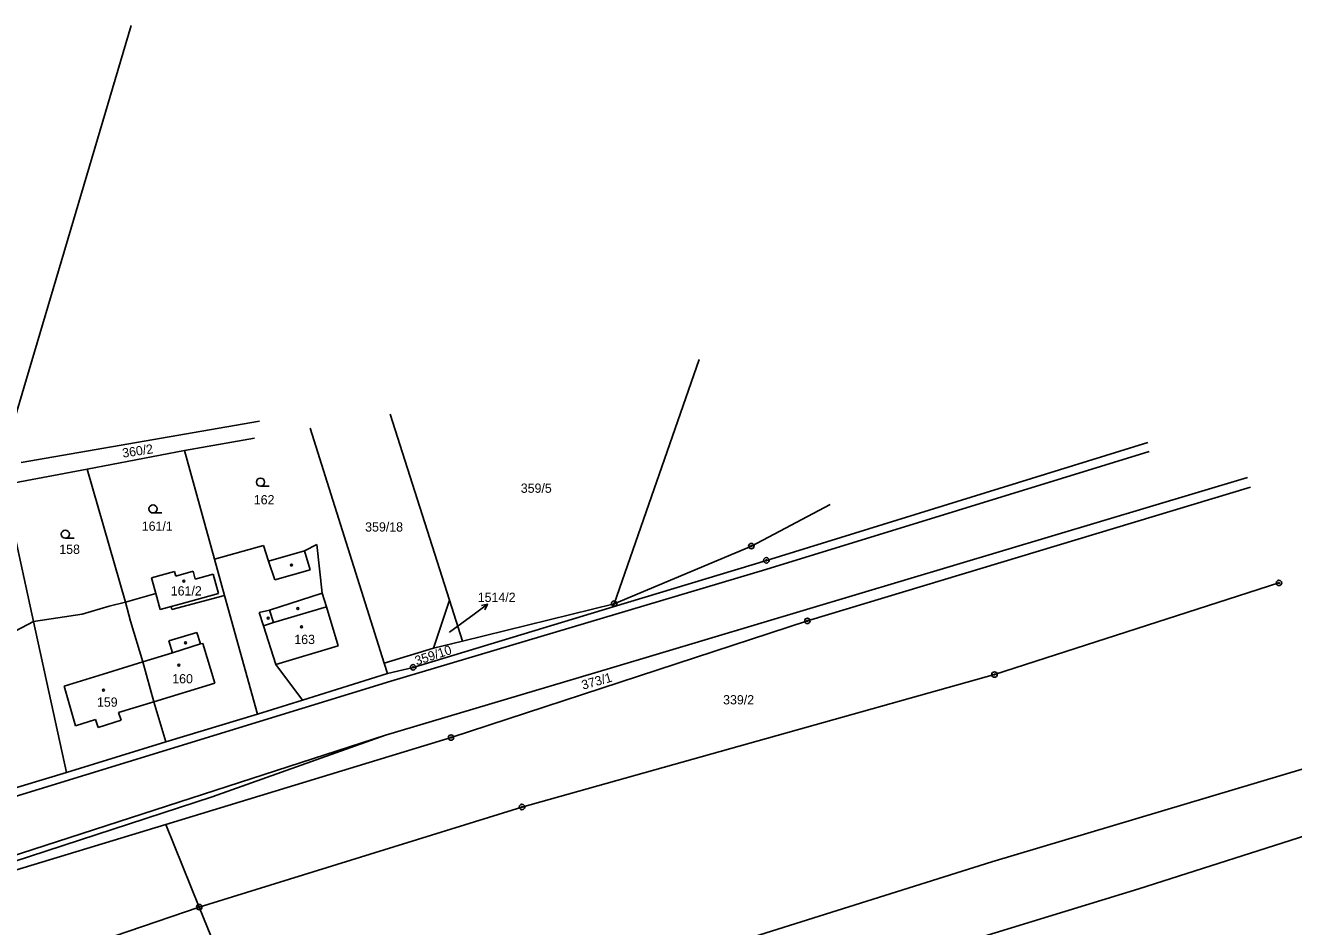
# Model space of a CAD drawing. Extents: x -762263 to -760336, y -1154405 to -1152076.
# Drawn here: x -761336.3 to -761103.3, y -1152340 to -1152174.4 of the extents above; entities that cross this region are included whole.
import ezdxf

# ---------------------------------------------------------------- set-up
doc = ezdxf.new("R2010")
doc.units = 0
for name, color, linetype in [('Vrstva 1', 7, 'Continuous'), ('Vrstva 16', 7, 'Continuous'), ('Vrstva 18', 7, 'Continuous'), ('Vrstva 19', 7, 'Continuous'), ('Vrstva 24', 7, 'Continuous'), ('Vrstva 25', 7, 'Continuous'), ('Vrstva 4', 7, 'Continuous'), ('Vrstva 6', 7, 'Continuous')]:
    doc.layers.add(name, color=color, linetype=linetype)

msp = doc.modelspace()

# ---------------------------------------------------------------- linework, layer by layer
at = {"layer": 'Vrstva 1'}
for p, q in [((-761228.13, -1152280.66), (-761212.53, -1152235.77)), ((-761269.26, -1152245.82), (-761258.4, -1152280)), ((-761337.08, -1152254.71), (-761293.3, -1152247.13)), ((-761283.95, -1152248.42), (-761270.38, -1152291.59)), ((-761307.04, -1152252.51), (-761294.21, -1152250.24)), ((-761200.17, -1152272.69), (-761130.07, -1152251.02)), ((-761324.92, -1152255.95), (-761307.04, -1152252.51)), ((-761301.53, -1152272.46), (-761307.04, -1152252.51)), ((-761340.24, -1152258.8), (-761324.92, -1152255.95)), ((-761324.92, -1152255.95), (-761317.91, -1152280.4)), ((-761340.24, -1152258.8), (-761334.77, -1152283.91)), ((-761192.63, -1152283.81), (-761111.25, -1152259.25)), ((-761188.42, -1152262.4), (-761202.93, -1152270.07)), ((-761301.53, -1152272.46), (-761292.55, -1152269.97)), ((-761292.55, -1152269.97), (-761291.6, -1152272.84)), ((-761284.99, -1152270.97), (-761282.73, -1152269.76)), ((-761282.73, -1152269.76), (-761281.76, -1152278.72)), ((-761202.93, -1152270.07), (-761228.13, -1152280.66)), ((-761299.69, -1152279.12), (-761301.53, -1152272.46)), ((-761291.6, -1152272.84), (-761284.99, -1152270.97)), ((-761200.17, -1152272.69), (-761228.32, -1152281.22)), ((-761308.9, -1152274.77), (-761313.11, -1152275.92)), ((-761308.68, -1152275.57), (-761308.9, -1152274.77)), ((-761305.46, -1152274.69), (-761308.68, -1152275.57)), ((-761305.46, -1152274.69), (-761305.07, -1152276.12)), ((-761313.11, -1152275.92), (-761312.33, -1152278.77)), ((-761305.07, -1152276.12), (-761301.79, -1152275.22)), ((-761301.79, -1152275.22), (-761300.84, -1152278.81)), ((-761158.26, -1152293.68), (-761106, -1152276.84)), ((-761312.33, -1152278.77), (-761317.91, -1152280.4)), ((-761312.33, -1152278.77), (-761311.52, -1152281.74)), ((-761309.36, -1152281.71), (-761299.69, -1152279.12)), ((-761300.84, -1152278.81), (-761307.66, -1152280.7)), ((-761299.69, -1152279.12), (-761293.66, -1152300.95)), ((-761281.76, -1152278.72), (-761281, -1152281.23)), ((-761325.83, -1152282.56), (-761320.87, -1152281.14)), ((-761320.87, -1152281.14), (-761317.91, -1152280.4)), ((-761317.91, -1152280.4), (-761316.96, -1152283.89)), ((-761311.52, -1152281.74), (-761309.51, -1152281.2)), ((-761309.51, -1152281.2), (-761307.66, -1152280.7)), ((-761309.36, -1152281.71), (-761309.51, -1152281.2)), ((-761281, -1152281.23), (-761278.82, -1152288.39)), ((-761228.32, -1152281.22), (-761265.07, -1152292.35)), ((-761258.4, -1152280), (-761256.01, -1152287.53)), ((-761228.32, -1152281.22), (-761228.13, -1152280.66)), ((-761334.77, -1152283.91), (-761338.19, -1152285.71)), ((-761334.77, -1152283.91), (-761325.83, -1152282.56)), ((-761334.77, -1152283.91), (-761328.72, -1152311.65)), ((-761316.96, -1152283.89), (-761314.7, -1152291.35)), ((-761258.09, -1152305.25), (-761192.63, -1152283.81)), ((-761278.82, -1152288.39), (-761290.27, -1152291.83)), ((-761314.7, -1152291.35), (-761312.67, -1152298.66)), ((-761290.27, -1152291.83), (-761285.36, -1152298.37)), ((-761285.36, -1152298.37), (-761269.77, -1152293.51)), ((-761270.38, -1152291.59), (-761269.77, -1152293.51)), ((-761265.07, -1152292.35), (-761269.77, -1152293.51)), ((-761245.06, -1152318.02), (-761158.26, -1152293.68)), ((-761312.67, -1152298.66), (-761310.5, -1152306.06)), ((-761293.66, -1152300.95), (-761285.36, -1152298.37)), ((-761310.5, -1152306.06), (-761293.66, -1152300.95)), ((-761310.49, -1152321.21), (-761258.09, -1152305.25)), ((-761328.72, -1152311.65), (-761310.5, -1152306.06)), ((-761346.8, -1152317.09), (-761328.72, -1152311.65)), ((-761304.35, -1152336.41), (-761245.06, -1152318.02)), ((-761310.49, -1152321.21), (-761342.06, -1152330.82)), ((-761304.35, -1152336.41), (-761310.49, -1152321.21)), ((-761375.09, -1152360.47), (-761304.35, -1152336.41)), ((-761304.35, -1152336.41), (-761295.51, -1152358.08))]:
    msp.add_line(p, q, dxfattribs=at)
at = {"layer": 'Vrstva 16'}
for p in [(-761251.404, -1152280.771), (-761258.35, -1152285.89)]:
    msp.add_line(p, (-761253.82, -1152282.55), dxfattribs=at)
msp.add_lwpolyline([(-761252.506, -1152280.962), (-761251.404, -1152280.771), (-761251.913, -1152281.767)], dxfattribs=at)
at = {"layer": 'Vrstva 24'}
for centre, radius in [((-761202.93, -1152270.07), 0.5), ((-761202.93, -1152270.07), 0.1), ((-761200.17, -1152272.69), 0.5), ((-761200.17, -1152272.69), 0.1), ((-761106, -1152276.84), 0.5), ((-761106, -1152276.84), 0.1), ((-761228.13, -1152280.66), 0.5), ((-761228.13, -1152280.66), 0.1), ((-761192.63, -1152283.81), 0.5), ((-761192.63, -1152283.81), 0.1), ((-761265.07, -1152292.35), 0.5), ((-761265.07, -1152292.35), 0.1), ((-761158.26, -1152293.68), 0.5), ((-761158.26, -1152293.68), 0.1), ((-761258.09, -1152305.25), 0.5), ((-761258.09, -1152305.25), 0.1), ((-761245.06, -1152318.02), 0.5), ((-761245.06, -1152318.02), 0.1), ((-761304.35, -1152336.41), 0.5), ((-761304.35, -1152336.41), 0.1)]:
    msp.add_circle(centre, radius, dxfattribs=at)
at = {"layer": 'Vrstva 25'}
for p, q in [((-761293.09, -1152259.07), (-761291.49, -1152259.07)), ((-761312.84, -1152263.99), (-761311.24, -1152263.99)), ((-761328.95, -1152268.64), (-761327.35, -1152268.64))]:
    msp.add_line(p, q, dxfattribs=at)
for centre, radius in [((-761293.09, -1152258.32), 0.75), ((-761312.84, -1152263.24), 0.75), ((-761328.95, -1152267.89), 0.75), ((-761287.41, -1152273.55), 0.175), ((-761307.19, -1152276.51), 0.175), ((-761286.24, -1152281.56), 0.175), ((-761291.67, -1152283.31), 0.175), ((-761285.56, -1152284.92), 0.175), ((-761306.86, -1152287.83), 0.175), ((-761308.11, -1152291.95), 0.175), ((-761321.94, -1152296.55), 0.175)]:
    msp.add_circle(centre, radius, dxfattribs=at)
at = {"layer": 'Vrstva 4'}
for p, q in [((-761283.98, -1152274.43), (-761284.99, -1152270.97)), ((-761291.6, -1152272.84), (-761290.47, -1152276.26)), ((-761290.47, -1152276.26), (-761283.98, -1152274.43)), ((-761291.44, -1152281.86), (-761281.76, -1152278.72)), ((-761293.33, -1152282.27), (-761291.44, -1152281.86)), ((-761290.69, -1152284.12), (-761291.44, -1152281.86)), ((-761281, -1152281.23), (-761290.69, -1152284.12)), ((-761292.54, -1152284.75), (-761293.33, -1152282.27)), ((-761290.69, -1152284.12), (-761292.54, -1152284.75)), ((-761304.81, -1152285.95), (-761309.92, -1152287.51)), ((-761304.11, -1152288.06), (-761304.81, -1152285.95)), ((-761290.27, -1152291.83), (-761292.54, -1152284.75)), ((-761309.92, -1152287.51), (-761309.26, -1152289.66)), ((-761309.26, -1152289.66), (-761304.11, -1152288.06)), ((-761304.11, -1152288.06), (-761303.67, -1152287.94)), ((-761303.67, -1152287.94), (-761301.48, -1152295.25)), ((-761314.7, -1152291.35), (-761309.26, -1152289.66)), ((-761329.16, -1152295.81), (-761322, -1152293.61)), ((-761322, -1152293.61), (-761314.7, -1152291.35)), ((-761327.11, -1152303.08), (-761329.16, -1152295.81)), ((-761301.48, -1152295.25), (-761312.67, -1152298.66)), ((-761312.67, -1152298.66), (-761319.16, -1152300.64)), ((-761319.16, -1152300.64), (-761318.72, -1152302.07)), ((-761323.39, -1152301.94), (-761327.11, -1152303.08)), ((-761322.94, -1152303.42), (-761323.39, -1152301.94)), ((-761318.72, -1152302.07), (-761322.94, -1152303.42))]:
    msp.add_line(p, q, dxfattribs=at)
at = {"layer": 'Vrstva 6'}
for p, q in [((-761316.84, -1152174.39), (-761340.8, -1152255.29)), ((-761129.86, -1152252.69), (-761200.24, -1152274.36)), ((-761228.8, -1152292.49), (-761111.79, -1152257.48)), ((-761200.24, -1152274.36), (-761269.17, -1152294.89)), ((-761261.32, -1152288.84), (-761258.4, -1152280)), ((-761228.13, -1152280.66), (-761256.01, -1152287.53)), ((-761261.32, -1152288.84), (-761270.38, -1152291.59)), ((-761256.01, -1152287.53), (-761261.32, -1152288.84)), ((-761228.8, -1152292.49), (-761270.12, -1152304.83)), ((-761358.61, -1152322.35), (-761269.17, -1152294.89)), ((-761270.12, -1152304.83), (-761358.12, -1152333.3)), ((-761270.12, -1152304.83), (-761301.99, -1152316.14)), ((-761131.77, -1152333.02), (-761052.68, -1152307.76)), ((-761158.78, -1152328.09), (-761101.12, -1152310.85)), ((-761301.99, -1152316.14), (-761373.97, -1152339.63)), ((-761233.23, -1152351.5), (-761158.78, -1152328.09)), ((-761203.4, -1152354.97), (-761131.77, -1152333.02))]:
    msp.add_line(p, q, dxfattribs=at)

# ---------------------------------------------------------------- texts
at = {"layer": 'Vrstva 16'}
msp.add_text('1514/2', height=1.7, dxfattribs=at).set_placement((-761253.187, -1152280.33))
at = {"layer": 'Vrstva 18'}
for s, rotation, p in [('360/2', 8.36518, (-761318.362, -1152253.837)), ('359/10', 18.27735, (-761264.417, -1152292.014)), ('373/1', 15.69904, (-761233.849, -1152296.471))]:
    msp.add_text(s, height=1.7, rotation=rotation, dxfattribs=at).set_placement(p)
for s, height, p in [('359/5', 1.7, (-761245.284, -1152260.28)), ('162', 1.7, (-761294.327, -1152262.4)), ('161/1', 1.7, (-761314.907, -1152267.26)), ('359/18', 1.7, (-761273.868, -1152267.4)), ('158', 1.7, (-761330.057, -1152271.5)), ('1514/2', 0.1, (-761258.559, -1152285.89)), ('339/2', 1.7, (-761208.113, -1152299.16))]:
    msp.add_text(s, height=height, dxfattribs=at).set_placement(p)
at = {"layer": 'Vrstva 19'}
for s, p in [('161/2', (-761309.577, -1152279.15)), ('163', (-761286.887, -1152288.07)), ('160', (-761309.307, -1152295.29)), ('159', (-761323.137, -1152299.59))]:
    msp.add_text(s, height=1.7, dxfattribs=at).set_placement(p)

doc.saveas('drawing.dxf')
